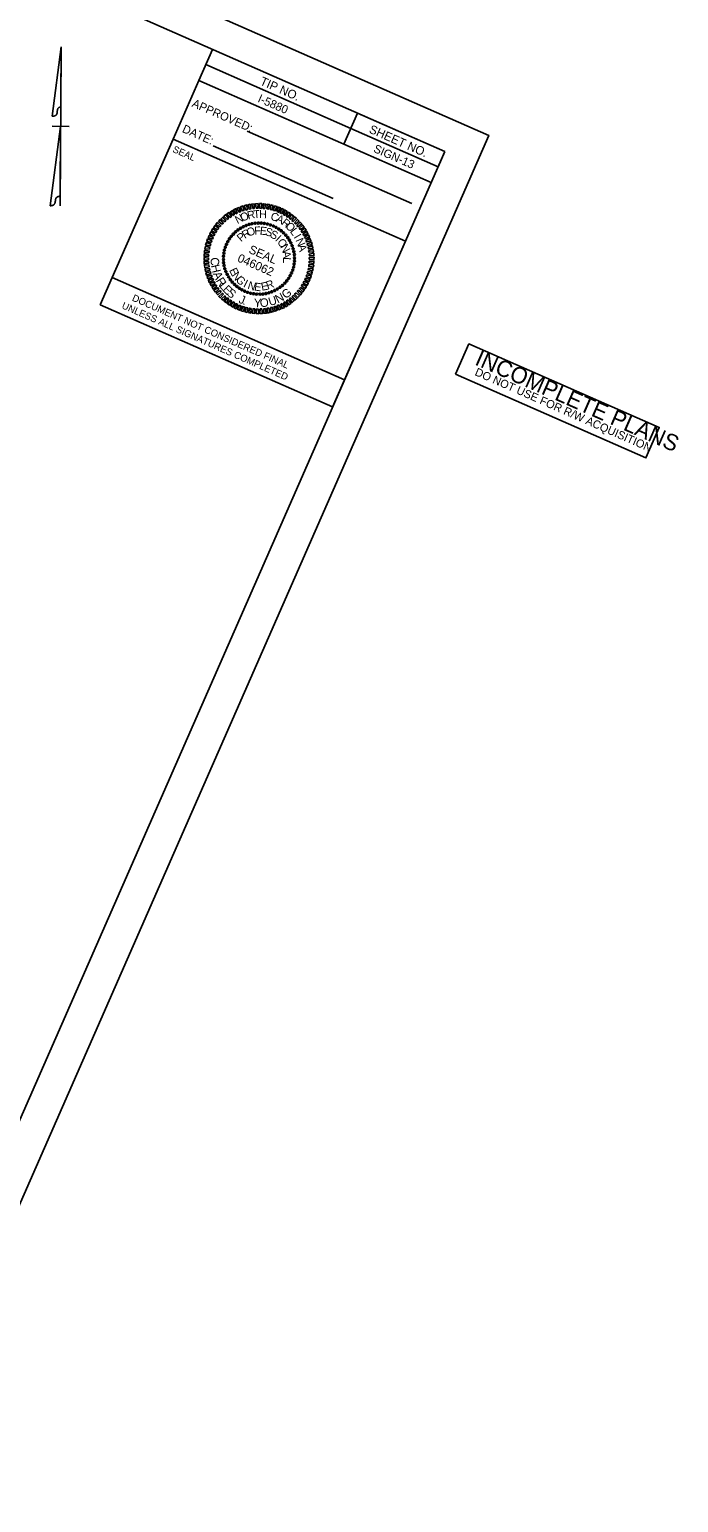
# Model space of a CAD drawing. Extents: x 1639021 to 1641149, y 842052 to 843739.
# Drawn here: x 1640670 to 1641149, y 842052 to 843138 of the extents above; entities that cross this region are included whole.
import ezdxf

# ---------------------------------------------------------------- set-up
doc = ezdxf.new("R2010")
doc.units = 0
for name, color, linetype in [('Default', 7, 'Continuous'), ('Old_Level_10', 7, 'Continuous'), ('Prop Easement Construction', 7, 'Continuous'), ('Prop Easement Permanent Drainage Utility Station Offsets', 7, 'Continuous'), ('Prop ROW CA Lines', 7, 'Continuous'), ('Prop ROW English Dual Dimension Text', 7, 'Continuous'), ('Prop ROW Marker CELL', 7, 'Continuous'), ('Prop ROW Station Offsets', 7, 'Continuous'), ('Prop ROW Text', 7, 'Continuous'), ('Scratch_Level_3', 7, 'Continuous'), ('Sheet Sticker Incomplete CELL', 7, 'Continuous')]:
    doc.layers.add(name, color=color, linetype=linetype)

msp = doc.modelspace()

# ---------------------------------------------------------------- linework, layer by layer
at = {"layer": 'Old_Level_10'}
for p, q in [((1640795.3, 843100), (1640805.3, 843122.9)), ((1640800.4, 843111.7), (1640907.3, 843064.7)), ((1640795.3, 843100), (1640966.5, 843024.8)), ((1640902.2, 843053.1), (1640912.2, 843075.9)), ((1640902.2, 843053.1), (1640912.2, 843075.9)), ((1640830.9, 843062.6), (1640952.3, 843009.3)), ((1640907.3, 843064.7), (1640971.6, 843036.5)), ((1640805.8, 843051.9), (1640894.4, 843013)), ((1640976.5, 843047.7), (1640976.5, 843047.7)), ((1640976.5, 843047.7), (1640976.5, 843047.7)), ((1640976.5, 843047.7), (1640976.5, 843047.7)), ((1640976.5, 843047.7), (1640976.5, 843047.7)), ((1640976.5, 843047.7), (1640976.5, 843047.7)), ((1640976.5, 843047.7), (1640976.5, 843047.7)), ((1640976.5, 843047.7), (1640976.5, 843047.7)), ((1640976.5, 843047.7), (1640976.5, 843047.7))]:
    msp.add_line(p, q, dxfattribs=at)
at = {"layer": 'Prop Easement Construction'}
for p, q in [((1640722.6, 842934.7), (1640731.5, 842954.8)), ((1640731.5, 842954.8), (1640902.7, 842879.6)), ((1640893.8, 842859.5), (1640722.6, 842934.7)), ((1640902.7, 842879.6), (1640893.8, 842859.4))]:
    msp.add_line(p, q, dxfattribs=at)
at = {"layer": 'Prop Easement Permanent Drainage Utility Station Offsets'}
msp.add_line((1640902.7, 842879.6), (1640731.5, 842954.8), dxfattribs=at)
at = {"layer": 'Prop ROW CA Lines'}
for p, q in [((1640776.3, 843056.8), (1640795.3, 843100)), ((1640820.6, 842986.9), (1640820.6, 842986.9)), ((1640822.3, 842988.5), (1640822.3, 842988.5)), ((1640824.1, 842990), (1640824.1, 842990)), ((1640826, 842991.2), (1640826, 842991.2)), ((1640828, 842992.4), (1640828, 842992.4)), ((1640830.1, 842993.3), (1640830.1, 842993.3)), ((1640832.3, 842994), (1640832.3, 842994)), ((1640834.5, 842994.5), (1640834.5, 842994.5)), ((1640836.8, 842994.9), (1640836.8, 842994.9)), ((1640839, 842995.1), (1640839, 842995.1)), ((1640841.3, 842995), (1640841.3, 842995)), ((1640843.6, 842994.7), (1640843.6, 842994.7)), ((1640845.8, 842994.2), (1640845.8, 842994.2)), ((1640848, 842993.7), (1640848, 842993.7)), ((1640850.2, 842992.8), (1640850.2, 842992.8)), ((1640852.2, 842991.8), (1640852.2, 842991.8)), ((1640854.2, 842990.6), (1640854.2, 842990.6)), ((1640856, 842989.3), (1640856, 842989.3)), ((1640857.8, 842987.8), (1640857.8, 842987.8)), ((1640859.3, 842986.1), (1640859.3, 842986.1)), ((1640814.2, 842975), (1640814.2, 842975)), ((1640814.7, 842977.2), (1640814.7, 842977.2)), ((1640815.6, 842979.4), (1640815.6, 842979.4)), ((1640816.6, 842981.4), (1640816.6, 842981.4)), ((1640817.8, 842983.4), (1640817.8, 842983.4)), ((1640819.1, 842985.2), (1640819.1, 842985.2)), ((1640860.8, 842984.4), (1640860.8, 842984.4)), ((1640862, 842982.4), (1640862, 842982.4)), ((1640863.2, 842980.4), (1640863.2, 842980.4)), ((1640864.1, 842978.3), (1640864.1, 842978.3)), ((1640864.9, 842976.1), (1640864.9, 842976.1)), ((1640813.4, 842970.5), (1640813.4, 842970.5)), ((1640813.4, 842968.2), (1640813.4, 842968.2)), ((1640813.5, 842965.9), (1640813.5, 842965.9)), ((1640813.7, 842972.7), (1640813.7, 842972.7)), ((1640839.6, 842968.8), (1640839.6, 842968.8)), ((1640865.4, 842973.9), (1640865.4, 842973.9)), ((1640865.6, 842964.8), (1640865.6, 842964.8)), ((1640865.7, 842971.7), (1640865.7, 842971.7)), ((1640865.8, 842967.1), (1640865.8, 842967.1)), ((1640865.9, 842969.4), (1640865.9, 842969.4)), ((1640813.9, 842963.6), (1640813.9, 842963.6)), ((1640814.4, 842961.4), (1640814.4, 842961.4)), ((1640815.2, 842959.2), (1640815.2, 842959.2)), ((1640816, 842957.2), (1640816, 842957.2)), ((1640817.2, 842955.2), (1640817.2, 842955.2)), ((1640818.4, 842953.2), (1640818.4, 842953.2)), ((1640861.4, 842954.2), (1640861.4, 842954.2)), ((1640862.6, 842956.2), (1640862.6, 842956.2)), ((1640863.6, 842958.2), (1640863.6, 842958.2)), ((1640864.5, 842960.4), (1640864.5, 842960.4)), ((1640865.1, 842962.6), (1640865.1, 842962.6)), ((1640819.9, 842951.5), (1640819.9, 842951.5)), ((1640821.5, 842949.8), (1640821.5, 842949.8)), ((1640823.2, 842948.3), (1640823.2, 842948.3)), ((1640825.1, 842947), (1640825.1, 842947)), ((1640827, 842945.8), (1640827, 842945.8)), ((1640829, 842944.8), (1640829, 842944.8)), ((1640831.2, 842943.9), (1640831.2, 842943.9)), ((1640833.4, 842943.3), (1640833.4, 842943.3)), ((1640835.7, 842942.8), (1640835.7, 842942.8)), ((1640837.9, 842942.6), (1640837.9, 842942.6)), ((1640840.2, 842942.5), (1640840.2, 842942.5)), ((1640842.5, 842942.7), (1640842.5, 842942.7)), ((1640844.8, 842943.1), (1640844.8, 842943.1)), ((1640847, 842943.6), (1640847, 842943.6)), ((1640849.2, 842944.3), (1640849.2, 842944.3)), ((1640851.2, 842945.2), (1640851.2, 842945.2)), ((1640853.2, 842946.4), (1640853.2, 842946.4)), ((1640855.2, 842947.6), (1640855.2, 842947.6)), ((1640856.9, 842949.1), (1640856.9, 842949.1)), ((1640858.6, 842950.6), (1640858.6, 842950.6)), ((1640860.1, 842952.4), (1640860.1, 842952.4))]:
    msp.add_line(p, q, dxfattribs=at)
for points in [[(1640776.3, 843056.8), (1640947.5, 842981.6), (1640902.7, 842879.6), (1640731.5, 842954.8)], [(1640827.3, 843003.9), (1640826.1, 843006.9), (1640827.7, 843007.6), (1640828.5, 843004.2)], [(1640829.9, 843004.6), (1640828.8, 843007.8), (1640830.5, 843008.3), (1640831.1, 843004.9)], [(1640832.3, 843005.3), (1640831.6, 843008.5), (1640833.2, 843008.9), (1640833.6, 843005.4)], [(1640835, 843005.6), (1640834.3, 843009), (1640836.1, 843009.1), (1640836.1, 843005.8)], [(1640837.5, 843005.9), (1640837.1, 843009.2), (1640838.9, 843009.3), (1640838.8, 843005.9)], [(1640840.1, 843006), (1640840, 843009.3), (1640841.7, 843009.3), (1640841.4, 843005.8)], [(1640842.7, 843005.8), (1640842.9, 843009.2), (1640844.5, 843009), (1640843.9, 843005.7)], [(1640845.3, 843005.5), (1640845.6, 843008.9), (1640847.4, 843008.6), (1640846.4, 843005.3)], [(1640847.9, 843005), (1640848.4, 843008.4), (1640850, 843007.9), (1640849.1, 843004.7)], [(1640850.3, 843004.3), (1640851.1, 843007.6), (1640852.8, 843007.2), (1640851.5, 843004)], [(1640812.3, 842994.1), (1640809.7, 842996.2), (1640811, 842997.5), (1640813.3, 842994.9)], [(1640814.2, 842995.8), (1640811.7, 842998.2), (1640813, 842999.4), (1640815.1, 842996.7)], [(1640816.1, 842997.6), (1640813.8, 843000), (1640815.2, 843001.2), (1640817.1, 842998.3)], [(1640818.1, 842999.2), (1640816, 843001.8), (1640817.5, 843002.7), (1640819.3, 842999.8)], [(1640820.4, 843000.5), (1640818.5, 843003.3), (1640820, 843004.3), (1640821.4, 843001.2)], [(1640822.6, 843001.8), (1640820.9, 843004.7), (1640822.4, 843005.5), (1640823.6, 843002.4)], [(1640825, 843002.9), (1640823.4, 843005.9), (1640825.1, 843006.5), (1640826.1, 843003.3)], [(1640852.8, 843003.6), (1640853.9, 843006.8), (1640855.5, 843006.1), (1640854, 843003)], [(1640855.1, 843002.6), (1640856.4, 843005.7), (1640858, 843005), (1640856.2, 843002)], [(1640857.5, 843001.4), (1640859, 843004.5), (1640860.4, 843003.5), (1640858.5, 843000.7)], [(1640859.6, 843000), (1640861.3, 843003), (1640862.8, 843002), (1640860.7, 842999.4)], [(1640861.9, 842998.5), (1640863.6, 843001.4), (1640865.1, 843000.3), (1640862.8, 842997.8)], [(1640863.9, 842996.9), (1640865.9, 842999.6), (1640867.2, 842998.5), (1640864.8, 842996.1)], [(1640865.7, 842995.1), (1640868.1, 842997.7), (1640869.2, 842996.5), (1640866.7, 842994.3)], [(1640805.4, 842983.1), (1640802.2, 842984.3), (1640802.9, 842985.9), (1640805.9, 842984.3)], [(1640806.4, 842985.5), (1640803.3, 842986.9), (1640804.1, 842988.5), (1640807, 842986.6)], [(1640807.6, 842987.7), (1640804.7, 842989.3), (1640805.6, 842990.9), (1640808.4, 842988.8)], [(1640809.1, 842990), (1640806.2, 842991.7), (1640807.2, 842993.2), (1640809.9, 842990.9)], [(1640810.7, 842992.1), (1640807.9, 842994), (1640808.9, 842995.4), (1640811.5, 842992.9)], [(1640867.5, 842993.3), (1640869.9, 842995.6), (1640871.1, 842994.3), (1640868.3, 842992.3)], [(1640869.3, 842991.2), (1640871.7, 842993.5), (1640872.8, 842992), (1640869.9, 842990.3)], [(1640870.6, 842989.2), (1640873.4, 842991.3), (1640874.3, 842989.7), (1640871.4, 842988.1)], [(1640872, 842986.9), (1640874.9, 842988.8), (1640875.7, 842987.2), (1640872.6, 842985.8)], [(1640873.2, 842984.6), (1640876.2, 842986.3), (1640876.9, 842984.7), (1640873.8, 842983.5)], [(1640802.8, 842973.2), (1640799.3, 842973.4), (1640799.6, 842975.1), (1640802.9, 842974.4)], [(1640803.2, 842975.8), (1640799.8, 842976.1), (1640800.2, 842977.9), (1640803.3, 842976.9)], [(1640803.7, 842978.3), (1640800.3, 842978.9), (1640800.9, 842980.6), (1640804, 842979.5)], [(1640804.4, 842980.7), (1640801.1, 842981.6), (1640801.7, 842983.3), (1640804.8, 842981.9)], [(1640874.2, 842982.2), (1640877.2, 842983.6), (1640877.9, 842982), (1640874.6, 842981.1)], [(1640875.2, 842979.8), (1640878.3, 842981), (1640878.8, 842979.3), (1640875.4, 842978.5)], [(1640875.8, 842977.3), (1640879, 842978.3), (1640879.4, 842976.5), (1640876, 842976.1)], [(1640876.2, 842974.8), (1640879.6, 842975.5), (1640879.9, 842973.7), (1640876.5, 842973.5)], [(1640802.6, 842970.6), (1640799.1, 842970.5), (1640799.2, 842972.3), (1640802.5, 842971.8)], [(1640802.5, 842967.9), (1640799.1, 842967.7), (1640799.1, 842969.5), (1640802.5, 842969.2)], [(1640802.6, 842965.5), (1640799.2, 842964.9), (1640799.2, 842966.7), (1640802.4, 842966.6)], [(1640803, 842962.8), (1640799.7, 842962.1), (1640799.4, 842963.9), (1640802.7, 842964.1)], [(1640876.4, 842964.4), (1640880, 842964.2), (1640879.6, 842962.5), (1640876.3, 842963.2)], [(1640876.6, 842972.1), (1640880, 842972.7), (1640880, 842970.9), (1640876.8, 842971)], [(1640876.6, 842967), (1640880.1, 842967), (1640880, 842965.3), (1640876.7, 842965.8)], [(1640876.7, 842969.6), (1640880.2, 842969.9), (1640880.1, 842968.1), (1640876.7, 842968.4)], [(1640803.4, 842960.3), (1640800.2, 842959.3), (1640799.9, 842961.1), (1640803.2, 842961.5)], [(1640804.1, 842957.8), (1640800.9, 842956.6), (1640800.5, 842958.3), (1640803.8, 842959.1)], [(1640805, 842955.4), (1640802, 842954), (1640801.3, 842955.6), (1640804.6, 842956.5)], [(1640806.1, 842953), (1640803, 842951.3), (1640802.4, 842952.9), (1640805.5, 842954.1)], [(1640873.9, 842954.5), (1640877.1, 842953.3), (1640876.4, 842951.7), (1640873.4, 842953.3)], [(1640874.8, 842956.9), (1640878.1, 842956), (1640877.5, 842954.3), (1640874.4, 842955.7)], [(1640875.5, 842959.3), (1640878.9, 842958.7), (1640878.4, 842957), (1640875.2, 842958.1)], [(1640876, 842961.8), (1640879.5, 842961.5), (1640879.1, 842959.7), (1640875.9, 842960.7)], [(1640807.3, 842950.7), (1640804.4, 842948.8), (1640803.6, 842950.4), (1640806.6, 842951.8)], [(1640808.6, 842948.4), (1640805.8, 842946.3), (1640805, 842947.9), (1640807.8, 842949.5)], [(1640810, 842946.3), (1640807.5, 842944.1), (1640806.4, 842945.6), (1640809.3, 842947.3)], [(1640811.7, 842944.3), (1640809.3, 842942), (1640808.1, 842943.3), (1640810.9, 842945.3)], [(1640813.5, 842942.5), (1640811.1, 842939.9), (1640810, 842941), (1640812.6, 842943.3)], [(1640866.9, 842943.5), (1640869.5, 842941.4), (1640868.3, 842940.1), (1640865.9, 842942.7)], [(1640868.6, 842945.5), (1640871.3, 842943.6), (1640870.3, 842942.2), (1640867.8, 842944.7)], [(1640870.2, 842947.6), (1640873, 842945.9), (1640872, 842944.4), (1640869.4, 842946.7)], [(1640871.6, 842949.9), (1640874.6, 842948.3), (1640873.7, 842946.7), (1640870.9, 842948.8)], [(1640872.8, 842952.1), (1640875.9, 842950.7), (1640875.1, 842949.1), (1640872.2, 842950.9)], [(1640815.3, 842940.7), (1640813.4, 842938), (1640812.1, 842939.1), (1640814.5, 842941.5)], [(1640817.4, 842939.1), (1640815.6, 842936.2), (1640814.1, 842937.2), (1640816.5, 842939.8)], [(1640819.6, 842937.5), (1640817.9, 842934.6), (1640816.4, 842935.5), (1640818.5, 842938.2)], [(1640821.8, 842936.2), (1640820.3, 842933.1), (1640818.8, 842934.1), (1640820.7, 842936.9)], [(1640824.1, 842935), (1640822.8, 842931.9), (1640821.2, 842932.6), (1640823, 842935.6)], [(1640826.4, 842934), (1640825.3, 842930.8), (1640823.8, 842931.5), (1640825.3, 842934.5)], [(1640828.9, 842933.2), (1640828.2, 842929.9), (1640826.4, 842930.4), (1640827.7, 842933.6)], [(1640831.4, 842932.6), (1640830.8, 842929.2), (1640829.2, 842929.7), (1640830.1, 842932.9)], [(1640833.9, 842932.1), (1640833.6, 842928.7), (1640831.9, 842929), (1640832.8, 842932.3)], [(1640836.5, 842931.8), (1640836.4, 842928.4), (1640834.7, 842928.6), (1640835.3, 842931.9)], [(1640839.2, 842931.6), (1640839.3, 842928.2), (1640837.6, 842928.3), (1640837.8, 842931.8)], [(1640841.7, 842931.7), (1640842.1, 842928.3), (1640840.3, 842928.3), (1640840.5, 842931.7)], [(1640844.3, 842932), (1640845, 842928.6), (1640843.1, 842928.5), (1640843.1, 842931.8)], [(1640846.9, 842932.3), (1640847.7, 842929.1), (1640846, 842928.7), (1640845.6, 842932.2)], [(1640849.3, 842933), (1640850.4, 842929.8), (1640848.7, 842929.3), (1640848.2, 842932.7)], [(1640851.9, 842933.7), (1640853.1, 842930.7), (1640851.5, 842930), (1640850.7, 842933.4)], [(1640854.2, 842934.7), (1640855.8, 842931.7), (1640854.2, 842931.1), (1640853.1, 842934.2)], [(1640856.6, 842935.8), (1640858.4, 842932.9), (1640856.8, 842932.1), (1640855.6, 842935.2)], [(1640858.9, 842937), (1640860.8, 842934.3), (1640859.3, 842933.3), (1640857.9, 842936.4)], [(1640861.1, 842938.4), (1640863.2, 842935.8), (1640861.7, 842934.8), (1640860, 842937.8)], [(1640863.1, 842940), (1640865.4, 842937.6), (1640864, 842936.4), (1640862.2, 842939.3)], [(1640865, 842941.8), (1640867.6, 842939.4), (1640866.2, 842938.2), (1640864.1, 842940.9)]]:
    msp.add_lwpolyline(points, close=True, dxfattribs=at)
for centre, major_axis in [((1640819.2, 842985.2), (-0.588, 0.471)), ((1640820.7, 842986.9), (-0.544, 0.52)), ((1640822.3, 842988.5), (-0.497, 0.566)), ((1640824.1, 842989.9), (-0.446, 0.607)), ((1640826, 842991.2), (-0.391, 0.643)), ((1640828, 842992.3), (-0.333, 0.675)), ((1640830.1, 842993.2), (-0.273, 0.702)), ((1640832.3, 842994), (-0.211, 0.723)), ((1640834.5, 842994.5), (-0.147, 0.738)), ((1640836.7, 842994.9), (-0.082, 0.748)), ((1640839, 842995), (-0.017, 0.753)), ((1640841.3, 842995), (0.049, 0.751)), ((1640843.6, 842994.7), (0.114, 0.744)), ((1640845.8, 842994.3), (0.179, 0.731)), ((1640848, 842993.6), (0.242, 0.713)), ((1640850.2, 842992.8), (0.303, 0.689)), ((1640852.2, 842991.8), (0.362, 0.66)), ((1640854.2, 842990.6), (0.418, 0.626)), ((1640856, 842989.3), (0.471, 0.588)), ((1640857.7, 842987.8), (0.52, 0.544)), ((1640859.3, 842986.1), (0.566, 0.497)), ((1640814.1, 842975), (-0.731, 0.179)), ((1640814.8, 842977.2), (-0.713, 0.242)), ((1640815.6, 842979.3), (-0.689, 0.303)), ((1640816.6, 842981.4), (-0.66, 0.362)), ((1640817.8, 842983.4), (-0.626, 0.418)), ((1640860.8, 842984.3), (0.607, 0.446)), ((1640862, 842982.4), (0.643, 0.391)), ((1640863.1, 842980.4), (0.675, 0.333)), ((1640864.1, 842978.3), (0.702, 0.273)), ((1640864.8, 842976.1), (0.723, 0.211)), ((1640865.3, 842973.9), (0.738, 0.147)), ((1640813.4, 842968.2), (-0.753, -0.017)), ((1640813.4, 842970.5), (-0.751, 0.049)), ((1640813.5, 842965.9), (-0.748, -0.082)), ((1640813.7, 842972.8), (-0.744, 0.114)), ((1640813.9, 842963.7), (-0.738, -0.147)), ((1640865.5, 842964.8), (0.744, -0.114)), ((1640865.7, 842971.7), (0.748, 0.082)), ((1640865.8, 842967.1), (0.751, -0.049)), ((1640865.8, 842969.4), (0.753, 0.017)), ((1640814.4, 842961.4), (-0.723, -0.211)), ((1640815.2, 842959.3), (-0.702, -0.273)), ((1640816.1, 842957.2), (-0.675, -0.333)), ((1640817.2, 842955.2), (-0.643, -0.391)), ((1640818.5, 842953.3), (-0.607, -0.446)), ((1640860.1, 842952.4), (0.588, -0.471)), ((1640861.4, 842954.2), (0.626, -0.418)), ((1640862.6, 842956.2), (0.66, -0.362)), ((1640863.6, 842958.2), (0.689, -0.303)), ((1640864.5, 842960.4), (0.713, -0.242)), ((1640865.1, 842962.6), (0.731, -0.179)), ((1640819.9, 842951.5), (-0.566, -0.497)), ((1640821.5, 842949.8), (-0.52, -0.544)), ((1640823.2, 842948.3), (-0.471, -0.588)), ((1640825.1, 842947), (-0.418, -0.626)), ((1640827, 842945.8), (-0.362, -0.66)), ((1640829.1, 842944.8), (-0.303, -0.689)), ((1640831.2, 842944), (-0.242, -0.713)), ((1640833.4, 842943.3), (-0.179, -0.731)), ((1640835.6, 842942.9), (-0.114, -0.744)), ((1640837.9, 842942.6), (-0.049, -0.751)), ((1640840.2, 842942.6), (0.017, -0.753)), ((1640842.5, 842942.7), (0.082, -0.748)), ((1640844.7, 842943.1), (0.147, -0.738)), ((1640847, 842943.6), (0.211, -0.723)), ((1640849.1, 842944.4), (0.273, -0.702)), ((1640851.2, 842945.3), (0.333, -0.675)), ((1640853.2, 842946.4), (0.391, -0.643)), ((1640855.1, 842947.7), (0.446, -0.607)), ((1640856.9, 842949.1), (0.497, -0.566)), ((1640858.6, 842950.7), (0.544, -0.52))]:
    msp.add_ellipse(centre, major_axis=major_axis, ratio=0.999708, dxfattribs=at)
at = {"layer": 'Prop ROW English Dual Dimension Text'}
for p, q in [((1640687.2, 843073.7), (1640693.8, 843124.7)), ((1640687.2, 843073.7), (1640693.8, 843124.7)), ((1640693, 843007.8), (1640693.8, 843124.7)), ((1640693.8, 843124.7), (1640693.5, 843080.3)), ((1640693.8, 843124.7), (1640693.5, 843080.3)), ((1640693.4, 843066.2), (1640685.8, 843007.8)), ((1640687.1, 843066.3), (1640699.7, 843066.2)), ((1640693, 843014.7), (1640693.4, 843066.2))]:
    msp.add_line(p, q, dxfattribs=at)
for points in [[(1640693.5, 843080.3), (1640691, 843080.6), (1640690.8, 843073.5), (1640687.2, 843073.7)], [(1640693.5, 843080.3), (1640691, 843080.6), (1640690.8, 843073.5), (1640687.2, 843073.7)], [(1640685.8, 843007.8), (1640689.4, 843007.6), (1640689.6, 843014.8), (1640693, 843014.7)]]:
    msp.add_open_spline(points, degree=2, dxfattribs=at)
at = {"layer": 'Prop ROW Marker CELL'}
msp.add_lwpolyline([(1640976.5, 843047.7), (1639603.8, 843650.7), (1639181.1, 842688.4), (1640553.8, 842085.4)], close=True, dxfattribs=at)
at = {"layer": 'Prop ROW Text'}
msp.add_lwpolyline([(1639463.6, 843738.4), (1641009, 843059.5), (1640566.6, 842052.4), (1639021.2, 842731.3)], close=True, dxfattribs=at)
at = {"layer": 'Scratch_Level_3'}
for p in [(1640912.2, 843075.9), (1640971.6, 843036.5)]:
    msp.add_line(p, (1640976.5, 843047.7), dxfattribs=at)
at = {"layer": 'Sheet Sticker Incomplete CELL'}
msp.add_lwpolyline([(1640984.5, 842883.6), (1640994.4, 842906), (1641134.6, 842844.5), (1641124.8, 842822)], close=True, dxfattribs=at)

# ---------------------------------------------------------------- texts
at = {"layer": 'Default'}
for s, rotation, p in [('C', 273.4848, (1640803.8, 842969.5)), ('H', 282.9285, (1640804.1, 842963.7)), ('A', 292.7683, (1640805.5, 842957.7)), ('R', 301.481, (1640807.6, 842952.6)), ('L', 308.8532, (1640809.9, 842948.7)), ('E', 315.0374, (1640812.3, 842945.6)), ('S', 322.044, (1640815.3, 842942.4)), ('N', 27.5138, (1640853.5, 842935.7)), ('G', 38.0847, (1640859.3, 842938.8)), ('J', 339.317, (1640824.2, 842936.4)), ('.', 344.4989, (1640827.2, 842935.1)), ('Y', 358.5275, (1640835.8, 842933.1)), ('O', 6.3262, (1640840.6, 842932.9)), ('U', 17.7197, (1640847.7, 842933.8))]:
    msp.add_text(s, height=6.27, rotation=rotation, dxfattribs=at).set_placement(p)
at = {"layer": 'Old_Level_10'}
for s, height, p in [('TIP NO.', 6.36, (1640839.8, 843097.2)), ('I-5880', 6.11, (1640838.2, 843084.5)), ('SHEET NO.', 6.36, (1640920.2, 843061.8)), ('SEAL', 5.09, (1640775.5, 843047.5)), ('SIGN-13', 6.11, (1640923.5, 843047.6))]:
    msp.add_text(s, height=height, rotation=336.2799, dxfattribs=at).set_placement(p)
at = {"layer": 'Prop Easement Construction'}
for s, p in [('DOCUMENT NOT CONSIDERED FINAL', (1640745.6, 842938)), ('UNLESS ALL SIGNATURES COMPLETED', (1640738, 842932.4))]:
    msp.add_text(s, height=5.141, rotation=336.285, dxfattribs=at).set_placement(p)
at = {"layer": 'Prop ROW CA Lines'}
for s, height, rotation, p in [('N', 5.9, 26.7084, (1640823.7, 842994.2)), ('O', 5.9, 19.5067, (1640827, 842996)), ('R', 5.9, 12.3054, (1640831.6, 842997.6)), ('T', 5.9, 5.1047, (1640835.8, 842998.4)), ('H', 5.9, 357.9044, (1640839.6, 842998.7)), ('C', 5.9, 343.5048, (1640847.7, 842997.5)), ('A', 5.9, 336.3052, (1640851.7, 842996.2)), ('R', 5.9, 321.906, (1640855.6, 842994.3)), ('P', 5.9, 40.6838, (1640826.4, 842980.8)), ('R', 5.9, 31.3246, (1640829.2, 842983.2)), ('O', 5.9, 21.9662, (1640831.9, 842984.9)), ('F', 5.9, 3.252, (1640836.3, 842986.4)), ('E', 5.9, 353.896, (1640840, 842986.6)), ('S', 5.9, 344.5405, (1640843.7, 842986.2)), ('S', 5.9, 335.1853, (1640847.2, 842984.8)), ('I', 5.9, 316.4745, (1640851.1, 842982.4)), ('O', 5.9, 314.7061, (1640858.6, 842992.3)), ('L', 5.9, 307.5058, (1640862.1, 842988.7)), ('I', 5.9, 300.3051, (1640865, 842984.8)), ('SEAL', 6.27, 336.2849, (1640831.5, 842973.3)), ('O', 5.9, 307.1184, (1640852.7, 842980.9)), ('N', 5.9, 297.7615, (1640855.1, 842977.6)), ('N', 5.9, 293.1038, (1640866.4, 842982.4)), ('A', 5.9, 285.9021, (1640868.1, 842978.4)), ('046062', 6.27, 336.2849, (1640823.2, 842966.9)), ('A', 5.9, 279.0452, (1640856.8, 842973.9)), ('L', 5.9, 269.6858, (1640857.3, 842969.8)), ('E', 5.9, 295.5618, (1640817.5, 842960.3)), ('N', 5.9, 304.9189, (1640819.3, 842956.5)), ('G', 5.9, 314.2752, (1640822, 842952.8)), ('I', 5.9, 332.9861, (1640827.6, 842948.3)), ('N', 5.9, 342.3413, (1640830.8, 842946.8)), ('E', 5.9, 351.6967, (1640835.8, 842945.4)), ('E', 5.9, 10.409, (1640841.7, 842945.1)), ('R', 5.9, 19.7663, (1640846, 842946))]:
    msp.add_text(s, height=height, rotation=rotation, dxfattribs=at).set_placement(p)
at = {"layer": 'Prop ROW Station Offsets'}
for s, p in [('APPROVED:', (1640789.7, 843081)), ('DATE:', (1640782.5, 843062.2))]:
    msp.add_text(s, height=6.11, rotation=336.2799, dxfattribs=at).set_placement(p)
at = {"layer": 'Sheet Sticker Incomplete CELL'}
for s, height, p in [('INCOMPLETE PLANS', 12.002, (1640998, 842891)), ('DO NOT USE FOR R/W ACQUISITION', 6.001, (1640998.2, 842883.1))]:
    msp.add_text(s, height=height, rotation=336.285, dxfattribs=at).set_placement(p)

doc.saveas('drawing.dxf')
